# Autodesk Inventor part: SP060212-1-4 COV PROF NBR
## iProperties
Created: 2012-06
Part Number: SP060212-1-4 COV PROF NBR
Material: Rubber
Document SubType Name: Modeling
Designer: Administrator
Density: 0.93 g/cm^3
Mass: 125.267 g
Surface Area: 992.866 cm^2
Volume: 134.695 cm^3
Author: Administrator
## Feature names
1. Extrusion1
